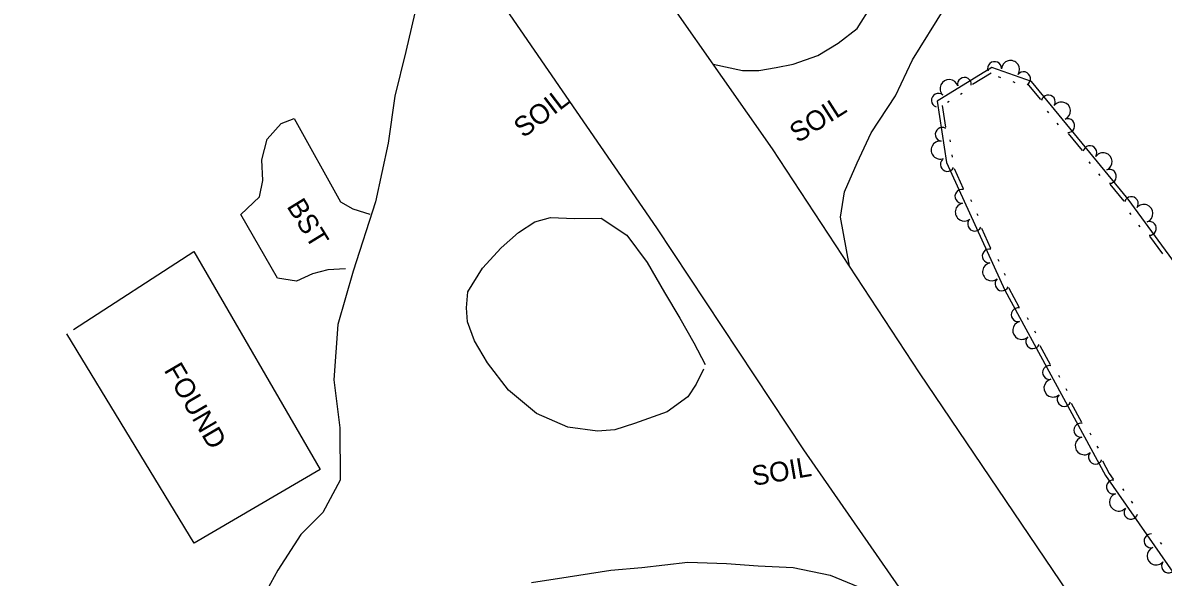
# Model space of a CAD drawing. Extents: x 2030130 to 2036320, y 723205 to 762423.
# Drawn here: x 2034332.5 to 2034546.3, y 759589.4 to 759693.3 of the extents above; entities that cross this region are included whole.
import ezdxf

# ---------------------------------------------------------------- set-up
doc = ezdxf.new("R2010")
doc.units = 0
for name, color, linetype in [('Draft_Station Labels Major', 7, 'Continuous'), ('Draft_Station Tics Major', 7, 'Continuous'), ('Exist Terrain Model Ground Surface', 7, 'Continuous'), ('Old_Level_23', 7, 'Continuous'), ('Old_Level_28', 7, 'Continuous')]:
    doc.layers.add(name, color=color, linetype=linetype)

msp = doc.modelspace()

# ---------------------------------------------------------------- linework, layer by layer
at = {"layer": 'Draft_Station Labels Major'}
for points in [[(2034673.1, 759374.03), (2034641.13, 759420.91), (2034612.37, 759462.99), (2034584.85, 759503.64), (2034556.5, 759545.4), (2034528.56, 759586.42), (2034500.61, 759627.72), (2034473.04, 759669.67), (2034444.47, 759710.51), (2034416.72, 759751.28), (2034388.73, 759792.32), (2034360.74, 759833.62)], [(2034339.29, 759819.51), (2034367.32, 759778.28), (2034395.22, 759737.17), (2034423.09, 759695.79), (2034451.3, 759654.89), (2034478.88, 759613.26), (2034507.24, 759572.41), (2034535.18, 759531.29), (2034563.29, 759490.2), (2034591.25, 759449.01), (2034619.59, 759406.87), (2034651.36, 759359.7)], [(2034461.93, 759685.55), (2034467.45, 759684.39), (2034470.48, 759684.34), (2034473.71, 759684.94), (2034476.94, 759685.54), (2034481.54, 759687.19), (2034485.39, 759689.48), (2034488.94, 759692.26), (2034491.58, 759696.47), (2034495.1, 759701.46), (2034498.26, 759707.8), (2034498.3, 759715.39), (2034497.82, 759720.13)], [(2034487.48, 759647.7), (2034485.78, 759656.85), (2034486.54, 759661.62), (2034488.93, 759667.03), (2034491.55, 759672.71), (2034496.14, 759679.63), (2034499.28, 759686.35), (2034505.38, 759696.13), (2034511.18, 759701.05), (2034519.44, 759708.47), (2034522.54, 759713.39)], [(2034406.4, 759697.05), (2034404.29, 759687.94), (2034402.24, 759679.54), (2034400.98, 759670.76), (2034398.6, 759659.72), (2034394.4, 759646.76), (2034391.51, 759636.74), (2034390.8, 759626.41), (2034391.91, 759617.38), (2034392.01, 759607.6), (2034388.72, 759601.52), (2034384.63, 759597.38), (2034380.26, 759590.7), (2034376.86, 759584.48), (2034371.89, 759577.33), (2034367.26, 759572.7), (2034359.83, 759567.87), (2034353.85, 759564.53), (2034347.15, 759563.4), (2034340.28, 759563.68), (2034331.95, 759563.03), (2034324.37, 759562.59)], [(2034392.99, 759647.22), (2034389.67, 759647.03), (2034386.8, 759646.27), (2034383.79, 759644.89), (2034380.21, 759645.46), (2034373.37, 759657.38), (2034376.85, 759660.69), (2034377.5, 759663.74), (2034377.29, 759667.62), (2034378.27, 759671.52), (2034380.91, 759674.4), (2034383.35, 759675.34), (2034392.05, 759659.77), (2034394.33, 759658.44), (2034396.52, 759657.72), (2034397.55, 759657.42)], [(2034460.08, 759628.4), (2034458.73, 759625.55), (2034457.15, 759623.22), (2034453.28, 759620.38), (2034447.2, 759618.19), (2034443.49, 759617.01), (2034440.24, 759616.75), (2034434.64, 759617.49), (2034428.78, 759620.05), (2034423.53, 759624.42), (2034419.59, 759629.58), (2034417.17, 759633.7), (2034415.87, 759637.25), (2034415.64, 759639.88), (2034415.91, 759642.91), (2034418.69, 759647.31), (2034422.15, 759651.13), (2034425.41, 759654), (2034428.51, 759655.97), (2034431.42, 759656.84), (2034435.91, 759656.65), (2034440.9, 759656.69), (2034445.75, 759653.52), (2034449.56, 759648.4), (2034452.77, 759642.77), (2034455.64, 759637.95), (2034458.28, 759633.31), (2034460.45, 759629.29)], [(2034427.85, 759588.4), (2034434.76, 759589.49), (2034442.74, 759590.73), (2034448.57, 759591.19), (2034457.15, 759592.22), (2034464.43, 759591.96), (2034470.33, 759591.52), (2034476.95, 759591.19), (2034483.83, 759589.77), (2034489.19, 759587.56)]]:
    msp.add_lwpolyline(points, dxfattribs=at)
at = {"layer": 'Draft_Station Tics Major'}
for points in [[(2034678.77, 759457.52), (2034629.19, 759530.12), (2034583.17, 759596.15), (2034555.6, 759638.55), (2034539.74, 759660.23), (2034521.63, 759682.3), (2034514.16, 759684.91), (2034503.93, 759678.63), (2034505.67, 759667.12), (2034516.62, 759643.18), (2034535.47, 759608.43), (2034554.89, 759580.65), (2034572.81, 759559.81), (2034594.96, 759529.87), (2034615.86, 759498.85), (2034654.18, 759442.62)], [(2034514.02, 759683.86), (2034510.52, 759681.72)], [(2034515.83, 759683.02), (2034515.44, 759683.16)], [(2034518.54, 759682.07), (2034518.15, 759682.21)], [(2034523.35, 759678.9), (2034521.14, 759681.6), (2034521, 759681.65)], [(2034508.64, 759680.08), (2034508.29, 759679.87)], [(2034504.88, 759677.8), (2034505.49, 759673.74)], [(2034506.19, 759678.58), (2034505.84, 759678.36)], [(2034524.86, 759676.42), (2034524.6, 759676.74)], [(2034526.68, 759674.2), (2034526.42, 759674.52)], [(2034506.27, 759671.37), (2034506.33, 759670.97)], [(2034531.16, 759669.39), (2034528.56, 759672.56)], [(2034506.7, 759668.53), (2034506.76, 759668.13)], [(2034532.66, 759666.91), (2034532.4, 759667.23)], [(2034507.09, 759665.98), (2034508.8, 759662.25)], [(2034534.49, 759664.69), (2034534.23, 759665.01)], [(2034538.97, 759659.88), (2034536.36, 759663.05)], [(2034510.19, 759660.19), (2034510.36, 759659.81)], [(2034511.39, 759657.57), (2034511.56, 759657.2)], [(2034540.31, 759657.37), (2034540.07, 759657.7)], [(2034512.21, 759654.79), (2034513.92, 759651.06)], [(2034542, 759655.05), (2034541.76, 759655.38)], [(2034546.21, 759649.99), (2034543.79, 759653.31)], [(2034515.31, 759649), (2034515.48, 759648.62)], [(2034516.51, 759646.39), (2034516.68, 759646.01)], [(2034517.33, 759643.61), (2034517.36, 759643.54), (2034519.25, 759640.05)], [(2034520.79, 759638.08), (2034520.98, 759637.72)], [(2034522.16, 759635.56), (2034522.35, 759635.2)], [(2034523.16, 759632.84), (2034525.12, 759629.23)], [(2034526.65, 759627.27), (2034526.85, 759626.9)], [(2034528.02, 759624.74), (2034528.22, 759624.38)], [(2034529.03, 759622.02), (2034530.99, 759618.42)], [(2034532.52, 759616.45), (2034532.72, 759616.09)], [(2034533.89, 759613.93), (2034534.09, 759613.57)], [(2034534.9, 759611.21), (2034536.17, 759608.86), (2034536.94, 759607.77)], [(2034538.68, 759605.98), (2034538.92, 759605.65)], [(2034540.33, 759603.63), (2034540.56, 759603.3)], [(2034545.73, 759595.9), (2034545.97, 759595.56)]]:
    msp.add_lwpolyline(points, dxfattribs=at)
for centre, radius, start, end in [((2034514.69, 759684.73), 1.3, 359.1421, 199.9387), ((2034517.67, 759684.55), 1.69, 326.6709, 174.7434), ((2034520.11, 759682.83), 1.3, 301.4756, 142.2722), ((2034506.17, 759680.97), 1.69, 17.4907, 225.5632), ((2034509.04, 759681.77), 1.3, 352.2955, 193.092), ((2034504.15, 759678.77), 1.3, 49.9619, 250.7585), ((2034524.77, 759678.47), 1.3, 327.8105, 168.6071), ((2034527.22, 759676.77), 1.69, 295.3393, 143.4118), ((2034528.41, 759674.03), 1.3, 270.1441, 110.9406), ((2034504.87, 759672.4), 1.3, 59.3575, 260.1541), ((2034504.49, 759669.44), 1.69, 84.5528, 292.6253), ((2034532.57, 759668.96), 1.3, 327.8105, 168.6071), ((2034535.03, 759667.26), 1.69, 295.3393, 143.4118), ((2034505.83, 759666.76), 1.3, 133.0251, 333.8217), ((2034536.22, 759664.52), 1.3, 270.1441, 110.9406), ((2034508.56, 759660.79), 1.3, 75.3587, 276.1552), ((2034540.34, 759659.42), 1.3, 324.6117, 165.4082), ((2034509.01, 759657.84), 1.69, 100.5539, 308.6264), ((2034542.69, 759657.58), 1.69, 292.1405, 140.213), ((2034510.95, 759655.57), 1.3, 133.0251, 333.8217), ((2034543.72, 759654.78), 1.3, 266.9452, 107.7418), ((2034513.68, 759649.6), 1.3, 75.3587, 276.1552), ((2034514.13, 759646.65), 1.69, 100.5539, 308.6264), ((2034516.07, 759644.38), 1.3, 133.0251, 333.8217), ((2034519.12, 759638.58), 1.3, 79.2495, 280.0461), ((2034519.77, 759635.66), 1.69, 104.4448, 312.5173), ((2034521.86, 759633.53), 1.3, 136.916, 337.7126), ((2034524.99, 759627.76), 1.3, 79.2495, 280.0461), ((2034525.63, 759624.85), 1.69, 104.4448, 312.5173), ((2034527.72, 759622.71), 1.3, 136.916, 337.7126), ((2034530.85, 759616.95), 1.3, 79.2495, 280.0461), ((2034531.5, 759614.03), 1.69, 104.4448, 312.5173), ((2034533.59, 759611.9), 1.3, 136.916, 337.7126), ((2034536.97, 759606.29), 1.3, 85.7211, 286.5177), ((2034537.94, 759603.47), 1.69, 110.9164, 318.9889), ((2034540.26, 759601.58), 1.3, 143.3876, 344.1841), ((2034544.02, 759596.2), 1.3, 85.7211, 286.5177), ((2034544.99, 759593.38), 1.69, 110.9164, 318.9889), ((2034547.31, 759591.5), 1.3, 143.3876, 344.1841)]:
    msp.add_arc(centre, radius, start, end, dxfattribs=at)
at = {"layer": 'Exist Terrain Model Ground Surface'}
msp.add_lwpolyline([(2034342, 759635.83), (2034364.56, 759650.43), (2034388.24, 759609.58), (2034364.61, 759595.8), (2034340.72, 759634.98)], dxfattribs=at)

# ---------------------------------------------------------------- texts
at = {"layer": 'Old_Level_23'}
for s, rotation, p in [('SOIL', 37.3221, (2034426.34, 759671.61)), ('SOIL', 32.5452, (2034477.78, 759670.69)), ('BST', 301.5759, (2034381.86, 759658.91)), ('SOIL', 9.7537, (2034469.49, 759606.49))]:
    msp.add_text(s, height=3.691, rotation=rotation, dxfattribs=at).set_placement(p)
at = {"layer": 'Old_Level_28'}
msp.add_text('FOUND', height=3.691, rotation=300.2416, dxfattribs=at).set_placement((2034358.84, 759628.21))

doc.saveas('drawing.dxf')
